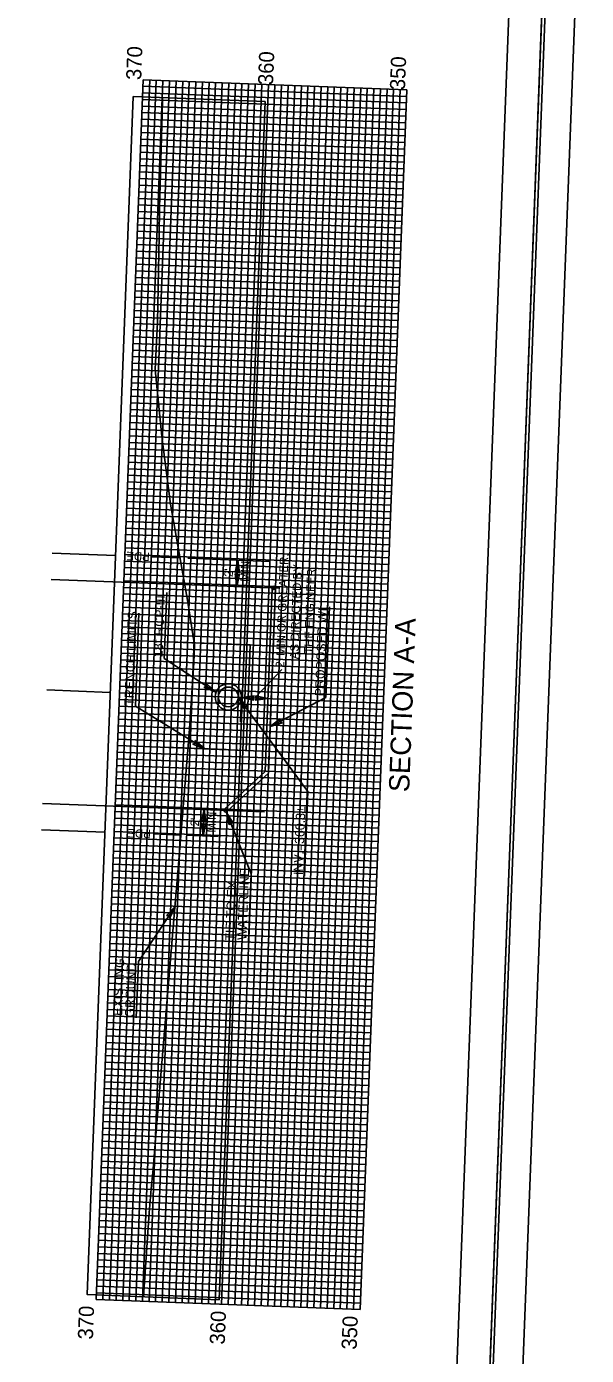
# Model space of a CAD drawing. Extents: x 2097431 to 2097897, y 685861 to 686794.
# Drawn here: x 2097727 to 2097896.7, y 686180.1 to 686582.8 of the extents above; entities that cross this region are included whole.
import ezdxf

# ---------------------------------------------------------------- set-up
doc = ezdxf.new("R2010")
doc.units = 0
for name, color, linetype in [('Exist XS Ground Line', 7, 'Continuous'), ('Old_Level_10', 7, 'Continuous'), ('Prop Dimension', 7, 'Continuous'), ('Prop Terminator CELL', 7, 'Continuous'), ('Scratch_Level_3', 7, 'Continuous'), ('Scratch_Level_4', 7, 'Continuous'), ('Scratch_Level_5', 7, 'Continuous'), ('Sheet DOT Grid CELL', 7, 'Continuous'), ('Sheet Plan And Profile CELL', 7, 'Continuous'), ('Sheet Plot Border Inside CELL', 7, 'Continuous'), ('Sheet Plot Border Outside CELL', 7, 'Continuous'), ('Sheet Profile CELL', 7, 'Continuous'), ('Sheet Profile Grid Major CELL', 7, 'Continuous'), ('Sheet Profile Grid Middle CELL', 7, 'Continuous'), ('Sheet Profile Grid Minor CELL', 7, 'Continuous')]:
    doc.layers.add(name, color=color, linetype=linetype)

msp = doc.modelspace()

# ---------------------------------------------------------------- linework, layer by layer
at = {"layer": 'Exist XS Ground Line'}
msp.add_lwpolyline([(2097762.46, 686197.84), (2097764.14, 686223.28), (2097764.76, 686230.59), (2097765.33, 686236.62), (2097766.55, 686251.79), (2097772.07, 686317.1), (2097772.88, 686326.43), (2097776.26, 686368.62), (2097777.68, 686389.99), (2097777.89, 686395.36), (2097775.73, 686408.95), (2097770.59, 686438.13), (2097768.03, 686458.58), (2097765.97, 686478.95), (2097766.71, 686493.22), (2097767.21, 686519.55), (2097767.28, 686527.8), (2097768.15, 686560.15), (2097768.24, 686561.28)], dxfattribs=at)
at = {"layer": 'Old_Level_10'}
for p, q in [((2097773.47, 686421.79), (2097765.02, 686422.11)), ((2097799.3, 686357.04), (2097801.43, 686412.71)), ((2097800.28, 686356.58), (2097802.43, 686412.67)), ((2097794.76, 686395.43), (2097777.78, 686396.08)), ((2097794.76, 686395.43), (2097793.54, 686363.45)), ((2097775.9, 686364.13), (2097793.54, 686363.45)), ((2097787, 686345.65), (2097799.3, 686357.04)), ((2097787.68, 686344.91), (2097800.28, 686356.58)), ((2097773.79, 686337.79), (2097765.33, 686338.12))]:
    msp.add_line(p, q, dxfattribs=at)
for centre, radius in [((2097801.93, 686412.69), 0.5), ((2097788.15, 686379.67), 4), ((2097788.15, 686379.67), 3), ((2097787.34, 686345.28), 0.5)]:
    msp.add_circle(centre, radius, dxfattribs=at)
at = {"layer": 'Prop Dimension'}
for p, q in [((2097775.84, 686421.7), (2097800.63, 686420.74)), ((2097791.05, 686421.11), (2097790.74, 686413.12)), ((2097768.75, 686391.29), (2097769.52, 686411.31)), ((2097800.33, 686412.75), (2097789.84, 686413.15)), ((2097817.71, 686379.5), (2097818.77, 686407.01)), ((2097759.97, 686376.84), (2097761.06, 686405.09)), ((2097768.75, 686391.29), (2097784.41, 686381.08)), ((2097804.34, 686387.93), (2097796.15, 686379.37)), ((2097812.27, 686350.99), (2097791.15, 686379.56)), ((2097792.15, 686379.52), (2097800.15, 686379.21)), ((2097817.71, 686379.5), (2097800.83, 686370.66)), ((2097759.97, 686376.84), (2097781, 686363.94)), ((2097812.27, 686350.99), (2097811.28, 686325.31)), ((2097785.49, 686345.35), (2097779.99, 686345.56)), ((2097780.82, 686345.53), (2097780.51, 686337.53)), ((2097795.07, 686326.02), (2097787.62, 686344.64)), ((2097775.34, 686337.73), (2097785.18, 686337.36)), ((2097794.27, 686305.33), (2097795.07, 686326.02)), ((2097760.88, 686299.5), (2097771.99, 686316.19)), ((2097760.22, 686282.35), (2097760.88, 686299.5))]:
    msp.add_line(p, q, dxfattribs=at)
at = {"layer": 'Prop Terminator CELL'}
for points in [[(2097790.26, 686417.37), (2097791.05, 686421.11), (2097791.57, 686417.3), (2097790.92, 686417.81)], [(2097791.53, 686416.86), (2097790.74, 686413.12), (2097790.22, 686416.93), (2097790.87, 686416.42)], [(2097781.61, 686383.68), (2097784.41, 686381.08), (2097780.87, 686382.58), (2097781.64, 686382.88)], [(2097792.87, 686376.14), (2097791.15, 686379.56), (2097793.94, 686376.91), (2097793.12, 686376.9)], [(2097795.89, 686378.73), (2097792.15, 686379.52), (2097795.96, 686380.04), (2097795.45, 686379.39)], [(2097796.41, 686380), (2097800.15, 686379.21), (2097796.34, 686378.69), (2097796.84, 686379.34)], [(2097804.46, 686371.84), (2097800.83, 686370.66), (2097803.87, 686373.01), (2097803.76, 686372.2)], [(2097778.13, 686366.46), (2097781, 686363.94), (2097777.42, 686365.35), (2097778.18, 686365.66)], [(2097780.02, 686341.79), (2097780.82, 686345.53), (2097781.34, 686341.72), (2097780.69, 686342.23)], [(2097788.42, 686340.9), (2097787.62, 686344.64), (2097789.65, 686341.37), (2097788.85, 686341.57)], [(2097781.3, 686341.27), (2097780.51, 686337.53), (2097779.99, 686341.34), (2097780.64, 686340.84)], [(2097769.37, 686313.42), (2097771.99, 686316.19), (2097770.45, 686312.67), (2097770.16, 686313.44)]]:
    msp.add_lwpolyline(points, close=True, dxfattribs=at)
at = {"layer": 'Scratch_Level_3'}
for p, q in [((2097753.97, 686422.53), (2097734.76, 686423.27)), ((2097803.72, 686412.62), (2097734.46, 686415.28)), ((2097752.38, 686381.04), (2097733.17, 686381.78)), ((2097790.98, 686374.99), (2097791.33, 686384.2)), ((2097794.61, 686379.42), (2097787.16, 686379.71)), ((2097799.07, 686344.83), (2097731.85, 686347.41)), ((2097750.76, 686338.68), (2097731.55, 686339.41))]:
    msp.add_line(p, q, dxfattribs=at)
at = {"layer": 'Scratch_Level_4'}
for p, q in [((2097788.77, 686395.66), (2097770.18, 686396.37)), ((2097788.31, 686383.67), (2097769.72, 686384.38)), ((2097792.15, 686379.52), (2097791.87, 686372.15)), ((2097794.15, 686379.44), (2097793.87, 686372.07)), ((2097788, 686375.68), (2097769.41, 686376.39)), ((2097787.54, 686363.68), (2097768.95, 686364.4))]:
    msp.add_line(p, q, dxfattribs=at)
at = {"layer": 'Scratch_Level_5'}
msp.add_lwpolyline([(2097785.35, 686196.96), (2097745.38, 686198.5), (2097759.31, 686561.62), (2097799.28, 686560.09)], close=True, dxfattribs=at)
at = {"layer": 'Sheet DOT Grid CELL'}
for p, q in [((2097748.13, 686197.02), (2097762.31, 686566.75)), ((2097768.12, 686196.26), (2097782.3, 686565.99)), ((2097788.11, 686195.49), (2097802.29, 686565.22)), ((2097808.09, 686194.73), (2097822.27, 686564.45)), ((2097828.08, 686193.96), (2097842.26, 686563.69)), ((2097761.93, 686556.76), (2097841.87, 686553.69)), ((2097761.16, 686536.77), (2097841.11, 686533.71)), ((2097760.4, 686516.79), (2097840.34, 686513.72)), ((2097759.63, 686496.8), (2097839.57, 686493.74)), ((2097758.87, 686476.82), (2097838.81, 686473.75)), ((2097758.1, 686456.83), (2097838.04, 686453.77)), ((2097757.33, 686436.85), (2097837.27, 686433.78)), ((2097756.57, 686416.86), (2097836.51, 686413.8)), ((2097755.8, 686396.88), (2097835.74, 686393.81)), ((2097755.03, 686376.89), (2097834.97, 686373.83)), ((2097754.27, 686356.91), (2097834.21, 686353.84)), ((2097753.5, 686336.92), (2097833.44, 686333.86)), ((2097752.73, 686316.94), (2097832.67, 686313.87)), ((2097751.97, 686296.95), (2097831.91, 686293.89)), ((2097751.2, 686276.97), (2097831.14, 686273.9)), ((2097750.43, 686256.98), (2097830.38, 686253.91)), ((2097749.67, 686237), (2097829.61, 686233.93)), ((2097748.9, 686217.01), (2097828.84, 686213.94)), ((2097748.13, 686197.02), (2097828.08, 686193.96))]:
    msp.add_line(p, q, dxfattribs=at)
at = {"layer": 'Sheet Plan And Profile CELL'}
msp.add_line((2097876.45, 686672.46), (2097853.46, 686072.9), dxfattribs=at)
msp.add_lwpolyline([(2097466.75, 686688.17), (2097443.76, 686088.61), (2097863.45, 686072.51), (2097886.44, 686672.07)], close=True, dxfattribs=at)
at = {"layer": 'Sheet Plot Border Inside CELL'}
msp.add_lwpolyline([(2097862.11, 686010.92), (2097887.65, 686677.03), (2097465.92, 686693.2), (2097440.38, 686027.09)], close=True, dxfattribs=at)
at = {"layer": 'Sheet Plot Border Outside CELL'}
msp.add_lwpolyline([(2097870.88, 686005.38), (2097896.7, 686678.48), (2097457.02, 686695.35), (2097431.2, 686022.24)], close=True, dxfattribs=at)
at = {"layer": 'Sheet Profile CELL'}
msp.add_line((2097863.45, 686072.51), (2097886.44, 686672.07), dxfattribs=at)
msp.add_lwpolyline([(2097466.75, 686688.17), (2097443.76, 686088.61), (2097863.45, 686072.51), (2097886.44, 686672.07)], close=True, dxfattribs=at)
at = {"layer": 'Sheet Profile Grid Major CELL'}
for points in [[(2097748.13, 686197.02), (2097762.31, 686566.75)], [(2097782.3, 686565.99), (2097768.12, 686196.26)], [(2097788.11, 686195.49), (2097802.29, 686565.22)], [(2097822.27, 686564.45), (2097808.09, 686194.73)], [(2097828.08, 686193.96), (2097842.26, 686563.69)], [(2097761.93, 686556.76), (2097841.87, 686553.69)], [(2097841.11, 686533.71), (2097761.16, 686536.77)], [(2097760.4, 686516.79), (2097840.34, 686513.72)], [(2097839.57, 686493.74), (2097759.63, 686496.8)], [(2097758.87, 686476.82), (2097838.81, 686473.75)], [(2097838.04, 686453.77), (2097758.1, 686456.83)], [(2097757.33, 686436.85), (2097837.27, 686433.78)], [(2097836.51, 686413.8), (2097756.57, 686416.86)], [(2097755.8, 686396.88), (2097835.74, 686393.81)], [(2097834.97, 686373.83), (2097755.03, 686376.89)], [(2097754.27, 686356.91), (2097834.21, 686353.84)], [(2097833.44, 686333.86), (2097753.5, 686336.92)], [(2097752.73, 686316.94), (2097832.67, 686313.87)], [(2097831.91, 686293.89), (2097751.97, 686296.95)], [(2097751.2, 686276.97), (2097831.14, 686273.9)], [(2097830.38, 686253.91), (2097750.43, 686256.98)], [(2097749.67, 686237), (2097829.61, 686233.93)], [(2097828.84, 686213.94), (2097748.9, 686217.01)]]:
    msp.add_lwpolyline(points, dxfattribs=at)
at = {"layer": 'Sheet Profile Grid Middle CELL'}
for p, q in [((2097758.13, 686196.64), (2097772.31, 686566.37)), ((2097792.29, 686565.6), (2097778.11, 686195.87)), ((2097798.1, 686195.11), (2097812.28, 686564.84)), ((2097832.26, 686564.07), (2097818.08, 686194.34)), ((2097751.58, 686286.96), (2097831.53, 686283.89)), ((2097830.76, 686263.91), (2097750.82, 686266.97)), ((2097750.05, 686246.99), (2097829.99, 686243.92)), ((2097829.23, 686223.94), (2097749.28, 686227)), ((2097748.52, 686207.02), (2097828.46, 686203.95))]:
    msp.add_line(p, q, dxfattribs=at)
for points in [[(2097762.31, 686566.75), (2097842.26, 686563.69)], [(2097841.49, 686543.7), (2097761.55, 686546.77)], [(2097760.78, 686526.78), (2097840.72, 686523.72)], [(2097839.96, 686503.73), (2097760.02, 686506.8)], [(2097759.25, 686486.81), (2097839.19, 686483.75)], [(2097838.42, 686463.76), (2097758.48, 686466.83)], [(2097757.72, 686446.84), (2097837.66, 686443.77)], [(2097836.89, 686423.79), (2097756.95, 686426.86)], [(2097756.18, 686406.87), (2097836.12, 686403.8)], [(2097835.36, 686383.82), (2097755.42, 686386.88)], [(2097754.65, 686366.9), (2097834.59, 686363.83)], [(2097833.82, 686343.85), (2097753.88, 686346.91)], [(2097753.12, 686326.93), (2097833.06, 686323.86)], [(2097832.29, 686303.88), (2097752.35, 686306.94)]]:
    msp.add_lwpolyline(points, dxfattribs=at)
at = {"layer": 'Sheet Profile Grid Minor CELL'}
for p, q in [((2097750.13, 686196.95), (2097764.31, 686566.68)), ((2097766.31, 686566.6), (2097752.13, 686196.87)), ((2097754.13, 686196.79), (2097768.31, 686566.52)), ((2097770.31, 686566.45), (2097756.13, 686196.72)), ((2097760.13, 686196.56), (2097774.31, 686566.29)), ((2097776.3, 686566.22), (2097762.12, 686196.49)), ((2097764.12, 686196.41), (2097778.3, 686566.14)), ((2097780.3, 686566.06), (2097766.12, 686196.33)), ((2097770.12, 686196.18), (2097784.3, 686565.91)), ((2097786.3, 686565.83), (2097772.12, 686196.1)), ((2097774.12, 686196.03), (2097788.3, 686565.76)), ((2097790.29, 686565.68), (2097776.11, 686195.95)), ((2097780.11, 686195.8), (2097794.29, 686565.53)), ((2097796.29, 686565.45), (2097782.11, 686195.72)), ((2097784.11, 686195.64), (2097798.29, 686565.37)), ((2097800.29, 686565.3), (2097786.11, 686195.57)), ((2097790.1, 686195.41), (2097804.28, 686565.14)), ((2097806.28, 686565.07), (2097792.1, 686195.34)), ((2097794.1, 686195.26), (2097808.28, 686564.99)), ((2097810.28, 686564.91), (2097796.1, 686195.18)), ((2097800.1, 686195.03), (2097814.28, 686564.76)), ((2097816.27, 686564.68), (2097802.1, 686194.96)), ((2097804.09, 686194.88), (2097818.27, 686564.61)), ((2097820.27, 686564.53), (2097806.09, 686194.8)), ((2097810.09, 686194.65), (2097824.27, 686564.38)), ((2097826.27, 686564.3), (2097812.09, 686194.57)), ((2097814.09, 686194.5), (2097828.27, 686564.22)), ((2097830.26, 686564.15), (2097816.08, 686194.42)), ((2097820.08, 686194.27), (2097834.26, 686563.99)), ((2097836.26, 686563.92), (2097822.08, 686194.19)), ((2097824.08, 686194.11), (2097838.26, 686563.84)), ((2097840.26, 686563.76), (2097826.08, 686194.04))]:
    msp.add_line(p, q, dxfattribs=at)
for points in [[(2097762.24, 686564.75), (2097842.18, 686561.69)], [(2097762.08, 686560.76), (2097842.03, 686557.69)], [(2097842.1, 686559.69), (2097762.16, 686562.76)], [(2097841.95, 686555.69), (2097762.01, 686558.76)], [(2097841.72, 686549.7), (2097761.78, 686552.76)], [(2097761.85, 686554.76), (2097841.8, 686551.7)], [(2097841.57, 686545.7), (2097761.62, 686548.77)], [(2097761.7, 686550.76), (2097841.64, 686547.7)], [(2097761.47, 686544.77), (2097841.41, 686541.7)], [(2097761.32, 686540.77), (2097841.26, 686537.71)], [(2097841.34, 686539.7), (2097761.39, 686542.77)], [(2097761.09, 686534.78), (2097841.03, 686531.71)], [(2097841.18, 686535.71), (2097761.24, 686538.77)], [(2097760.93, 686530.78), (2097840.88, 686527.71)], [(2097840.95, 686529.71), (2097761.01, 686532.78)], [(2097840.8, 686525.71), (2097760.86, 686528.78)], [(2097840.57, 686519.72), (2097760.63, 686522.78)], [(2097760.7, 686524.78), (2097840.65, 686521.72)], [(2097840.42, 686515.72), (2097760.47, 686518.79)], [(2097760.55, 686520.79), (2097840.49, 686517.72)], [(2097760.32, 686514.79), (2097840.26, 686511.72)], [(2097760.17, 686510.79), (2097840.11, 686507.73)], [(2097840.19, 686509.73), (2097760.24, 686512.79)], [(2097840.03, 686505.73), (2097760.09, 686508.8)], [(2097839.8, 686499.73), (2097759.86, 686502.8)], [(2097759.94, 686504.8), (2097839.88, 686501.73)], [(2097839.65, 686495.74), (2097759.71, 686498.8)], [(2097759.79, 686500.8), (2097839.73, 686497.74)], [(2097759.56, 686494.81), (2097839.5, 686491.74)], [(2097759.4, 686490.81), (2097839.34, 686487.74)], [(2097839.42, 686489.74), (2097759.48, 686492.81)], [(2097839.27, 686485.74), (2097759.33, 686488.81)], [(2097839.04, 686479.75), (2097759.1, 686482.81)], [(2097759.17, 686484.81), (2097839.11, 686481.75)], [(2097838.88, 686475.75), (2097758.94, 686478.82)], [(2097759.02, 686480.82), (2097838.96, 686477.75)], [(2097758.79, 686474.82), (2097838.73, 686471.75)], [(2097758.64, 686470.82), (2097838.58, 686467.76)], [(2097838.65, 686469.76), (2097758.71, 686472.82)], [(2097838.5, 686465.76), (2097758.56, 686468.82)], [(2097838.27, 686459.76), (2097758.33, 686462.83)], [(2097758.41, 686464.83), (2097838.35, 686461.76)], [(2097838.12, 686455.77), (2097758.18, 686458.83)], [(2097758.25, 686460.83), (2097838.19, 686457.76)], [(2097758.02, 686454.83), (2097837.96, 686451.77)], [(2097757.87, 686450.84), (2097837.81, 686447.77)], [(2097837.89, 686449.77), (2097757.95, 686452.84)], [(2097837.73, 686445.77), (2097757.79, 686448.84)], [(2097837.5, 686439.78), (2097757.56, 686442.84)], [(2097757.64, 686444.84), (2097837.58, 686441.78)], [(2097837.35, 686435.78), (2097757.41, 686438.85)], [(2097757.49, 686440.85), (2097837.43, 686437.78)], [(2097757.26, 686434.85), (2097837.2, 686431.78)], [(2097757.1, 686430.85), (2097837.04, 686427.79)], [(2097837.12, 686429.79), (2097757.18, 686432.85)], [(2097836.97, 686425.79), (2097757.03, 686428.85)], [(2097836.74, 686419.79), (2097756.8, 686422.86)], [(2097756.87, 686424.86), (2097836.81, 686421.79)], [(2097836.58, 686415.8), (2097756.64, 686418.86)], [(2097756.72, 686420.86), (2097836.66, 686417.79)], [(2097756.49, 686414.86), (2097836.43, 686411.8)], [(2097756.34, 686410.87), (2097836.28, 686407.8)], [(2097836.35, 686409.8), (2097756.41, 686412.87)], [(2097836.2, 686405.8), (2097756.26, 686408.87)], [(2097835.97, 686399.81), (2097756.03, 686402.87)], [(2097756.11, 686404.87), (2097836.05, 686401.81)], [(2097835.82, 686395.81), (2097755.88, 686398.88)], [(2097755.95, 686400.87), (2097835.89, 686397.81)], [(2097755.72, 686394.88), (2097835.66, 686391.81)], [(2097755.57, 686390.88), (2097835.51, 686387.82)], [(2097835.59, 686389.81), (2097755.65, 686392.88)], [(2097835.43, 686385.82), (2097755.49, 686388.88)], [(2097835.2, 686379.82), (2097755.26, 686382.89)], [(2097755.34, 686384.89), (2097835.28, 686381.82)], [(2097835.05, 686375.82), (2097755.11, 686378.89)], [(2097755.19, 686380.89), (2097835.13, 686377.82)], [(2097754.96, 686374.89), (2097834.9, 686371.83)], [(2097754.8, 686370.9), (2097834.74, 686367.83)], [(2097834.82, 686369.83), (2097754.88, 686372.9)], [(2097834.67, 686365.83), (2097754.73, 686368.9)], [(2097834.44, 686359.84), (2097754.5, 686362.9)], [(2097754.57, 686364.9), (2097834.51, 686361.84)], [(2097834.28, 686355.84), (2097754.34, 686358.91)], [(2097754.42, 686360.9), (2097834.36, 686357.84)], [(2097754.19, 686354.91), (2097834.13, 686351.84)], [(2097754.04, 686350.91), (2097833.98, 686347.85)], [(2097834.05, 686349.84), (2097754.11, 686352.91)], [(2097833.9, 686345.85), (2097753.96, 686348.91)], [(2097833.67, 686339.85), (2097753.73, 686342.92)], [(2097753.81, 686344.92), (2097833.75, 686341.85)], [(2097833.52, 686335.85), (2097753.58, 686338.92)], [(2097753.65, 686340.92), (2097833.59, 686337.85)], [(2097753.42, 686334.92), (2097833.36, 686331.86)], [(2097753.27, 686330.93), (2097833.21, 686327.86)], [(2097833.29, 686329.86), (2097753.35, 686332.92)], [(2097833.13, 686325.86), (2097753.19, 686328.93)], [(2097832.9, 686319.87), (2097752.96, 686322.93)], [(2097753.04, 686324.93), (2097832.98, 686321.86)], [(2097832.75, 686315.87), (2097752.81, 686318.93)], [(2097752.89, 686320.93), (2097832.83, 686317.87)], [(2097752.66, 686314.94), (2097832.6, 686311.87)], [(2097752.5, 686310.94), (2097832.44, 686307.87)], [(2097832.52, 686309.87), (2097752.58, 686312.94)], [(2097832.37, 686305.88), (2097752.43, 686308.94)], [(2097832.14, 686299.88), (2097752.2, 686302.95)], [(2097752.27, 686304.95), (2097832.21, 686301.88)], [(2097831.99, 686295.88), (2097752.04, 686298.95)], [(2097752.12, 686300.95), (2097832.06, 686297.88)], [(2097751.89, 686294.95), (2097831.83, 686291.89)], [(2097751.74, 686290.96), (2097831.68, 686287.89)], [(2097831.76, 686289.89), (2097751.81, 686292.95)], [(2097831.6, 686285.89), (2097751.66, 686288.96)], [(2097831.37, 686279.9), (2097751.43, 686282.96)], [(2097751.51, 686284.96), (2097831.45, 686281.89)], [(2097831.22, 686275.9), (2097751.28, 686278.96)], [(2097751.35, 686280.96), (2097831.3, 686277.9)], [(2097830.99, 686269.9), (2097751.05, 686272.97)], [(2097751.12, 686274.97), (2097831.07, 686271.9)], [(2097830.84, 686265.91), (2097750.89, 686268.97)], [(2097750.97, 686270.97), (2097830.91, 686267.9)], [(2097750.74, 686264.97), (2097830.68, 686261.91)], [(2097750.59, 686260.98), (2097830.53, 686257.91)], [(2097830.61, 686259.91), (2097750.66, 686262.98)], [(2097830.45, 686255.91), (2097750.51, 686258.98)], [(2097830.22, 686249.92), (2097750.28, 686252.98)], [(2097750.36, 686254.98), (2097830.3, 686251.92)], [(2097830.07, 686245.92), (2097750.13, 686248.99)], [(2097750.2, 686250.98), (2097830.15, 686247.92)], [(2097749.97, 686244.99), (2097829.92, 686241.92)], [(2097749.82, 686240.99), (2097829.76, 686237.93)], [(2097829.84, 686239.92), (2097749.9, 686242.99)], [(2097829.69, 686235.93), (2097749.74, 686238.99)], [(2097829.46, 686229.93), (2097749.51, 686233)], [(2097749.59, 686235), (2097829.53, 686231.93)], [(2097829.3, 686225.94), (2097749.36, 686229)], [(2097749.44, 686231), (2097829.38, 686227.93)], [(2097749.21, 686225), (2097829.15, 686221.94)], [(2097749.05, 686221.01), (2097829, 686217.94)], [(2097829.07, 686219.94), (2097749.13, 686223.01)], [(2097828.92, 686215.94), (2097748.98, 686219.01)], [(2097828.69, 686209.95), (2097748.75, 686213.01)], [(2097748.82, 686215.01), (2097828.77, 686211.95)], [(2097828.54, 686205.95), (2097748.59, 686209.02)], [(2097748.67, 686211.01), (2097828.61, 686207.95)], [(2097748.44, 686205.02), (2097828.38, 686201.95)], [(2097748.29, 686201.02), (2097828.23, 686197.96)], [(2097828.31, 686199.95), (2097748.36, 686203.02)], [(2097828.15, 686195.96), (2097748.21, 686199.02)]]:
    msp.add_lwpolyline(points, dxfattribs=at)

# ---------------------------------------------------------------- texts
at = {"layer": 'Old_Level_10'}
for s, height, rotation, p in [('370', 4.586, 87.8037, (2097761.73, 686566.59)), ('360', 4.586, 87.8037, (2097801.7, 686565.05)), ('350', 4.586, 87.8037, (2097841.68, 686563.52)), ('PDE', 2.58, 177.8037, (2097764.39, 686423.4)), ("2' MIN OR GREATER, ", 2.5797, 87.8037, (2097805.08, 686388.52)), ("2'", 2.58, 87.8037, (2097789.48, 686415.98)), ('MIN', 2.58, 87.8037, (2097794.35, 686414.51)), ('AS DIRECTED BY', 2.5797, 87.8037, (2097809.37, 686391.07)), ('THE ENGINEER', 2.5797, 87.8037, (2097813.63, 686392.71)), ('18" RCP-III', 2.7985, 87.8037, (2097768.19, 686391.67)), ('PROPOSED WL', 2.7985, 87.8037, (2097817.18, 686379.83)), ('TRENCH LIMITS', 2.7985, 87.8037, (2097759.41, 686376.94)), ('SECTION A-A', 6.1805, 87.8037, (2097842.96, 686350.71)), ('INV.=360.3%%P', 2.7985, 87.8037, (2097810.72, 686325.62)), ("2'", 2.58, 87.8037, (2097779.24, 686340.4)), ('MIN', 2.58, 87.8037, (2097784.26, 686338.51)), ('PDE', 2.58, 177.8037, (2097764.71, 686339.41)), ('WATERLINE', 2.798, 87.8037, (2097793.64, 686305.92)), ('TIE TO EX.', 2.798, 87.8037, (2097790, 686305.72)), ('EXISTING', 2.798, 87.8037, (2097755.95, 686282.95)), ('GROUND', 2.798, 87.8037, (2097759.57, 686282.45)), ('370', 4.586, 87.8037, (2097747.09, 686184.83)), ('360', 4.586, 87.8037, (2097787.06, 686183.3)), ('350', 4.586, 87.8037, (2097827.03, 686181.77))]:
    msp.add_text(s, height=height, rotation=rotation, dxfattribs=at).set_placement(p)

doc.saveas('drawing.dxf')
